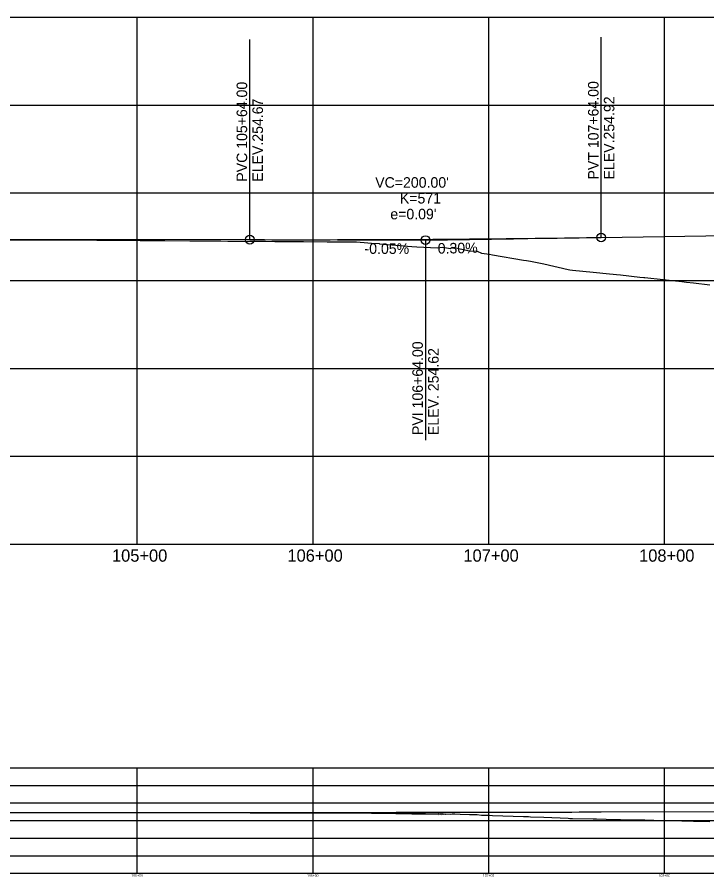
# Model space of a CAD drawing. Extents: x 1932071 to 1934815, y 598385 to 598883.
# Drawn here: x 1932824.3 to 1933216.8, y 598385.1 to 598874.6 of the extents above; entities that cross this region are included whole.
import ezdxf

# ---------------------------------------------------------------- set-up
doc = ezdxf.new("R2010")
doc.units = 0
for name, color, linetype in [('R_Axis', 7, 'Continuous'), ('R_Axis Annot', 7, 'Continuous'), ('R_Exist Surface', 7, 'Continuous'), ('R_Grid', 7, 'Continuous'), ('R_Vert Alg', 7, 'Continuous'), ('R_Vert Alg Annot', 7, 'Continuous')]:
    doc.layers.add(name, color=color, linetype=linetype)

msp = doc.modelspace()

# ---------------------------------------------------------------- linework, layer by layer
at = {"layer": 'R_Axis'}
for p, q in [((1932092.67, 598574.55), (1934792.67, 598574.55)), ((1932092.67, 598387.17), (1934792.67, 598387.17))]:
    msp.add_line(p, q, dxfattribs=at)
at = {"layer": 'R_Exist Surface'}
for points in [[(1932814.89, 598747.79), (1932826.42, 598747.78), (1932832.78, 598747.81), (1932836.43, 598747.8), (1932852.83, 598747.78), (1932857.17, 598747.8), (1932857.96, 598747.79), (1932868.1, 598747.71), (1932869.7, 598747.7), (1932879.49, 598747.62), (1932881.22, 598747.61), (1932882.23, 598747.6), (1932894.35, 598747.51), (1932894.75, 598747.5), (1932901.03, 598747.46), (1932902.89, 598747.44), (1932907.25, 598747.39), (1932908.37, 598747.39), (1932922.56, 598747.27), (1932932.04, 598747.19), (1932940.15, 598747.16), (1932944.1, 598747.13), (1932956.85, 598747.04), (1932965.63, 598746.98), (1932970.93, 598746.94), (1932980.53, 598746.9), (1932987.16, 598746.85), (1933000.63, 598746.73), (1933004.3, 598746.72), (1933008.7, 598746.69), (1933017.44, 598746.65), (1933023.92, 598746.14), (1933025.86, 598745.98), (1933030.23, 598745.62), (1933030.51, 598745.6), (1933039.79, 598744.83), (1933046.47, 598744.24), (1933048.87, 598744.01), (1933051.76, 598743.87), (1933063.54, 598743.27), (1933066.35, 598743.53), (1933070.97, 598742.87), (1933071.76, 598743.67), (1933073.3, 598743.34), (1933076.42, 598742.66), (1933081.76, 598741.57), (1933086.1, 598741.39), (1933088.5, 598740.2), (1933093.03, 598739.55), (1933094.83, 598739.24), (1933112.39, 598736.21), (1933114.09, 598735.95), (1933115.31, 598735.76), (1933116.37, 598735.57), (1933124.11, 598734.16), (1933137.9, 598730.93), (1933138.76, 598730.72), (1933140.28, 598730.6), (1933152.06, 598729.35), (1933153.96, 598729.2), (1933159.43, 598728.63), (1933165.34, 598727.97), (1933167.7, 598727.78), (1933178.62, 598726.57), (1933180.97, 598726.38), (1933181.48, 598726.33), (1933191.9, 598725.13), (1933195.34, 598724.84), (1933202.5, 598724.03), (1933205.17, 598723.71), (1933209.27, 598723.34), (1933218.42, 598722.26)], [(1932814.89, 598421.81), (1932826.42, 598421.81), (1932832.78, 598421.82), (1932836.43, 598421.82), (1932852.83, 598421.81), (1932857.17, 598421.82), (1932857.96, 598421.81), (1932868.1, 598421.8), (1932869.7, 598421.8), (1932879.49, 598421.78), (1932881.22, 598421.78), (1932882.23, 598421.78), (1932894.35, 598421.76), (1932894.75, 598421.76), (1932901.03, 598421.75), (1932902.89, 598421.74), (1932907.25, 598421.73), (1932908.37, 598421.73), (1932922.56, 598421.71), (1932932.04, 598421.69), (1932940.15, 598421.69), (1932944.1, 598421.68), (1932956.85, 598421.66), (1932965.63, 598421.65), (1932970.93, 598421.64), (1932980.53, 598421.64), (1932987.16, 598421.63), (1933000.63, 598421.6), (1933004.3, 598421.6), (1933008.7, 598421.59), (1933017.44, 598421.59), (1933023.92, 598421.48), (1933025.86, 598421.45), (1933030.23, 598421.38), (1933030.51, 598421.38), (1933039.79, 598421.22), (1933046.47, 598421.1), (1933048.87, 598421.06), (1933051.76, 598421.03), (1933063.54, 598420.91), (1933066.35, 598420.96), (1933070.97, 598420.83), (1933071.76, 598420.99), (1933073.3, 598420.92), (1933076.42, 598420.79), (1933081.76, 598420.57), (1933086.1, 598420.53), (1933088.5, 598420.3), (1933093.03, 598420.17), (1933094.83, 598420.1), (1933112.39, 598419.5), (1933114.09, 598419.45), (1933115.31, 598419.41), (1933116.37, 598419.37), (1933124.11, 598419.09), (1933137.9, 598418.44), (1933138.76, 598418.4), (1933140.28, 598418.38), (1933152.06, 598418.13), (1933153.96, 598418.1), (1933159.43, 598417.98), (1933165.34, 598417.85), (1933167.7, 598417.81), (1933178.62, 598417.57), (1933180.97, 598417.53), (1933181.48, 598417.52), (1933191.9, 598417.28), (1933195.34, 598417.22), (1933202.5, 598417.06), (1933205.17, 598417), (1933209.27, 598416.92), (1933218.42, 598416.71)]]:
    msp.add_lwpolyline(points, dxfattribs=at)
at = {"layer": 'R_Grid'}
for p, q in [((1932092.67, 598874.55), (1934792.67, 598874.55)), ((1932092.67, 598874.55), (1934792.67, 598874.55)), ((1932892.67, 598574.55), (1932892.67, 598874.55)), ((1932992.67, 598574.55), (1932992.67, 598874.55)), ((1933092.67, 598574.55), (1933092.67, 598874.55)), ((1933192.67, 598574.55), (1933192.67, 598874.55)), ((1932092.67, 598824.55), (1934792.67, 598824.55)), ((1932092.67, 598774.55), (1934792.67, 598774.55)), ((1932092.67, 598724.55), (1934792.67, 598724.55)), ((1932092.67, 598674.55), (1934792.67, 598674.55)), ((1932092.67, 598624.55), (1934792.67, 598624.55)), ((1932092.67, 598447.17), (1934792.67, 598447.17)), ((1932092.67, 598447.17), (1934792.67, 598447.17)), ((1932892.67, 598387.17), (1932892.67, 598447.17)), ((1932992.67, 598387.17), (1932992.67, 598447.17)), ((1933092.67, 598387.17), (1933092.67, 598447.17)), ((1933192.67, 598387.17), (1933192.67, 598447.17)), ((1932092.67, 598437.17), (1934792.67, 598437.17)), ((1932092.67, 598427.17), (1934792.67, 598427.17)), ((1932092.67, 598417.17), (1934792.67, 598417.17)), ((1932092.67, 598407.17), (1934792.67, 598407.17)), ((1932092.67, 598397.17), (1934792.67, 598397.17))]:
    msp.add_line(p, q, dxfattribs=at)
at = {"layer": 'R_Vert Alg'}
for p, q in [((1933156.67, 598749.16), (1933340.67, 598751.92)), ((1932384.22, 598749.34), (1932956.67, 598747.91)), ((1933006.67, 598747.79), (1933056.67, 598747.66)), ((1933056.67, 598747.66), (1933106.67, 598748.41)), ((1933156.67, 598422.09), (1933340.67, 598422.64)), ((1932384.22, 598422.12), (1932956.67, 598421.84)), ((1933006.67, 598421.81), (1933056.67, 598421.79)), ((1933056.67, 598421.79), (1933106.67, 598421.94))]:
    msp.add_line(p, q, dxfattribs=at)
for points in [[(1932956.67, 598747.91), (1932960.83, 598747.9), (1932965, 598747.9), (1932969.17, 598747.89), (1932973.33, 598747.88), (1932977.5, 598747.88), (1932981.67, 598747.88), (1932985.83, 598747.88), (1932990, 598747.88), (1932994.17, 598747.88), (1932998.33, 598747.88), (1933002.5, 598747.89), (1933006.67, 598747.9), (1933010.83, 598747.91), (1933015, 598747.92), (1933019.17, 598747.93), (1933023.33, 598747.94), (1933027.5, 598747.96), (1933031.67, 598747.97), (1933035.83, 598747.99), (1933040, 598748.01), (1933044.17, 598748.03), (1933048.33, 598748.05), (1933052.5, 598748.08), (1933060.83, 598748.13), (1933065, 598748.16), (1933069.17, 598748.19), (1933073.33, 598748.22), (1933077.5, 598748.25), (1933081.67, 598748.28), (1933085.83, 598748.32), (1933090, 598748.36), (1933094.17, 598748.4), (1933098.33, 598748.44), (1933102.5, 598748.48), (1933106.67, 598748.52), (1933110.83, 598748.57), (1933115, 598748.61), (1933119.17, 598748.66), (1933123.33, 598748.71), (1933127.5, 598748.76), (1933131.67, 598748.82), (1933135.83, 598748.87), (1933140, 598748.93), (1933144.17, 598748.98), (1933148.33, 598749.04), (1933152.5, 598749.1), (1933156.67, 598749.16)], [(1932956.67, 598421.84), (1932960.83, 598421.84), (1932965, 598421.84), (1932969.17, 598421.83), (1932973.33, 598421.83), (1932977.5, 598421.83), (1932981.67, 598421.83), (1932985.83, 598421.83), (1932990, 598421.83), (1932994.17, 598421.83), (1932998.33, 598421.83), (1933002.5, 598421.83), (1933006.67, 598421.84), (1933010.83, 598421.84), (1933015, 598421.84), (1933019.17, 598421.84), (1933023.33, 598421.84), (1933027.5, 598421.85), (1933031.67, 598421.85), (1933035.83, 598421.85), (1933040, 598421.86), (1933044.17, 598421.86), (1933048.33, 598421.87), (1933052.5, 598421.87), (1933060.83, 598421.88), (1933065, 598421.89), (1933069.17, 598421.89), (1933073.33, 598421.9), (1933077.5, 598421.91), (1933081.67, 598421.91), (1933085.83, 598421.92), (1933090, 598421.93), (1933094.17, 598421.94), (1933098.33, 598421.94), (1933102.5, 598421.95), (1933106.67, 598421.96), (1933110.83, 598421.97), (1933115, 598421.98), (1933119.17, 598421.99), (1933123.33, 598422), (1933127.5, 598422.01), (1933131.67, 598422.02), (1933135.83, 598422.03), (1933140, 598422.04), (1933144.17, 598422.05), (1933148.33, 598422.06), (1933152.5, 598422.08), (1933156.67, 598422.09)]]:
    msp.add_lwpolyline(points, dxfattribs=at)
at = {"layer": 'R_Vert Alg Annot'}
for p, q in [((1933156.67, 598779.16), (1933156.67, 598863.16)), ((1932956.67, 598777.91), (1932956.67, 598861.91)), ((1932956.67, 598747.91), (1932956.67, 598777.91)), ((1933156.67, 598749.16), (1933156.67, 598779.16)), ((1933056.67, 598747.66), (1933056.67, 598717.66)), ((1933056.67, 598717.66), (1933056.67, 598633.66))]:
    msp.add_line(p, q, dxfattribs=at)
for centre in [(1932956.67, 598747.91), (1933156.67, 598749.16), (1933056.67, 598747.66)]:
    msp.add_circle(centre, 2.5, dxfattribs=at)

# ---------------------------------------------------------------- texts
at = {"layer": 'R_Axis Annot'}
for s, height, p in [('105+00', 7, (1932878.23, 598564.55)), ('106+00', 7, (1932978.09, 598564.55)), ('107+00', 7, (1933078.23, 598564.55)), ('108+00', 7, (1933178.23, 598564.55)), ('105+00', 1.4, (1932889.3, 598385.17)), ('106+00', 1.4, (1932989.27, 598385.17)), ('107+00', 1.4, (1933089.3, 598385.17)), ('108+00', 1.4, (1933189.3, 598385.17))]:
    msp.add_text(s, height=height, dxfattribs=at).set_placement(p)
at = {"layer": 'R_Vert Alg Annot'}
for s, height, rotation, p in [('PVC 105+64.00', 6, 90, (1932955.17, 598780.91)), ('PVT 107+64.00', 6, 90, (1933155.17, 598782.16)), ('ELEV.254.92', 6, 90, (1933164.17, 598782.16)), ('ELEV.254.67', 6, 90, (1932964.17, 598780.91)), ('-0.05%', 6, 359.8568, (1933021.95, 598739.83)), ('0.30%', 6, 0.8594, (1933063.67, 598739.93)), ('PVI 106+64.00', 6, 90, (1933055.17, 598636.66)), ('ELEV. 254.62', 6, 90, (1933064.17, 598636.66)), ('0.30%', 1.203, 0.1719, (1933063.67, 598420.24)), ('0.30%', 1.203, 0.1719, (1933063.67, 598420.24))]:
    msp.add_text(s, height=height, rotation=rotation, dxfattribs=at).set_placement(p)
for s, p in [("VC=200.00'", (1933028.05, 598777.47)), ('K=571', (1933042.08, 598768.47)), ("e=0.09'", (1933036.65, 598759.47))]:
    msp.add_text(s, height=6, dxfattribs=at).set_placement(p)

doc.saveas('drawing.dxf')
